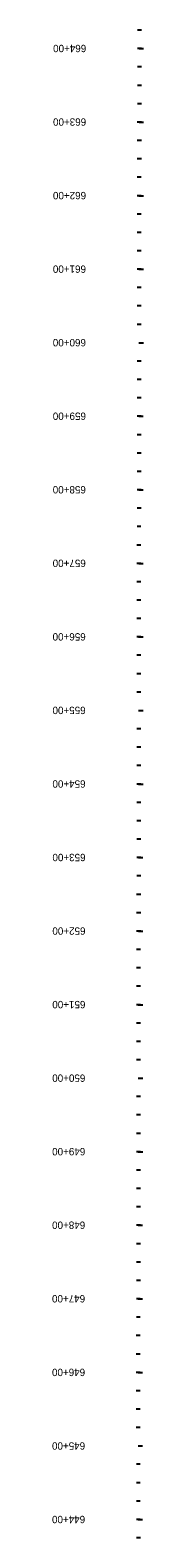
# Model space of a CAD drawing. Extents: x 16453950 to 16454580, y 7022804 to 7039381.
# Drawn here: x 16454322 to 16454446, y 7031115 to 7033165 of the extents above; entities that cross this region are included whole.
import ezdxf

# ---------------------------------------------------------------- set-up
doc = ezdxf.new("R2010")
doc.units = 0
doc.layers.add('TextAlignmentLrg', color=7, linetype='Continuous')
doc.layers.add('TextAlignmentSml', color=7, linetype='Continuous')

msp = doc.modelspace()

# ---------------------------------------------------------------- linework, layer by layer
at = {"layer": 'TextAlignmentLrg'}
for p, q in [((16454442.8, 7033139.6), (16454437.3, 7033139.6)), ((16454442.7, 7033039.6), (16454437.2, 7033039.6)), ((16454442.6, 7032939.6), (16454437.1, 7032939.6)), ((16454442.5, 7032839.6), (16454437.1, 7032839.6)), ((16454439.4, 7032739.6), (16454445.5, 7032739.6)), ((16454442.4, 7032639.6), (16454436.9, 7032639.6)), ((16454442.3, 7032539.6), (16454436.8, 7032539.6)), ((16454442.2, 7032439.6), (16454436.7, 7032439.6)), ((16454442.1, 7032339.6), (16454436.6, 7032339.6)), ((16454439, 7032239.6), (16454445.1, 7032239.6)), ((16454441.9, 7032139.6), (16454436.5, 7032139.6)), ((16454441.9, 7032039.6), (16454436.4, 7032039.6)), ((16454441.8, 7031939.6), (16454436.3, 7031939.6)), ((16454441.7, 7031839.6), (16454436.2, 7031839.6)), ((16454438.5, 7031739.6), (16454444.7, 7031739.6)), ((16454441.5, 7031639.6), (16454436.1, 7031639.6)), ((16454441.4, 7031539.6), (16454436, 7031539.6)), ((16454441.3, 7031439.6), (16454435.9, 7031439.6)), ((16454441.3, 7031339.6), (16454435.8, 7031339.6)), ((16454438.2, 7031239.6), (16454444.4, 7031239.6)), ((16454441.3, 7031139.6), (16454435.9, 7031139.6))]:
    msp.add_line(p, q, dxfattribs=at)
at = {"layer": 'TextAlignmentSml'}
for p, q in [((16454442.8, 7033164.6), (16454437.3, 7033164.6)), ((16454439.7, 7033139.6), (16454445.8, 7033139.6)), ((16454442.8, 7033114.6), (16454437.3, 7033114.6)), ((16454442.7, 7033089.6), (16454437.3, 7033089.6)), ((16454442.7, 7033064.6), (16454437.3, 7033064.6)), ((16454439.6, 7033039.6), (16454445.8, 7033039.6)), ((16454442.7, 7033014.6), (16454437.2, 7033014.6)), ((16454442.7, 7032989.6), (16454437.2, 7032989.6)), ((16454442.6, 7032964.6), (16454437.2, 7032964.6)), ((16454439.5, 7032939.6), (16454445.7, 7032939.6)), ((16454442.6, 7032914.6), (16454437.1, 7032914.6)), ((16454442.6, 7032889.6), (16454437.1, 7032889.6)), ((16454442.5, 7032864.6), (16454437.1, 7032864.6)), ((16454439.5, 7032839.6), (16454445.6, 7032839.6)), ((16454442.5, 7032814.6), (16454437, 7032814.6)), ((16454442.5, 7032789.6), (16454437, 7032789.6)), ((16454442.5, 7032764.6), (16454437, 7032764.6)), ((16454439.4, 7032739.6), (16454445.5, 7032739.6)), ((16454442.4, 7032714.6), (16454437, 7032714.6)), ((16454442.4, 7032689.6), (16454436.9, 7032689.6)), ((16454442.4, 7032664.6), (16454436.9, 7032664.6)), ((16454439.3, 7032639.6), (16454445.4, 7032639.6)), ((16454442.3, 7032614.6), (16454436.9, 7032614.6)), ((16454442.3, 7032589.6), (16454436.9, 7032589.6)), ((16454442.3, 7032564.6), (16454436.8, 7032564.6)), ((16454439.2, 7032539.6), (16454445.3, 7032539.6)), ((16454442.3, 7032514.6), (16454436.8, 7032514.6)), ((16454442.2, 7032489.6), (16454436.8, 7032489.6)), ((16454442.2, 7032464.6), (16454436.7, 7032464.6)), ((16454439.1, 7032439.6), (16454445.2, 7032439.6)), ((16454442.2, 7032414.6), (16454436.7, 7032414.6)), ((16454442.1, 7032389.6), (16454436.7, 7032389.6)), ((16454442.1, 7032364.6), (16454436.7, 7032364.6)), ((16454439, 7032339.6), (16454445.2, 7032339.6)), ((16454442.1, 7032314.6), (16454436.6, 7032314.6)), ((16454442.1, 7032289.6), (16454436.6, 7032289.6)), ((16454442, 7032264.6), (16454436.6, 7032264.6)), ((16454439, 7032239.6), (16454445.1, 7032239.6)), ((16454442, 7032214.6), (16454436.5, 7032214.6)), ((16454442, 7032189.6), (16454436.5, 7032189.6)), ((16454442, 7032164.6), (16454436.5, 7032164.6)), ((16454438.9, 7032139.6), (16454445, 7032139.6)), ((16454441.9, 7032114.6), (16454436.5, 7032114.6)), ((16454441.9, 7032089.6), (16454436.4, 7032089.6)), ((16454441.9, 7032064.6), (16454436.4, 7032064.6)), ((16454438.8, 7032039.6), (16454444.9, 7032039.6)), ((16454441.8, 7032014.6), (16454436.4, 7032014.6)), ((16454441.8, 7031989.6), (16454436.3, 7031989.6)), ((16454441.8, 7031964.6), (16454436.3, 7031964.6)), ((16454438.7, 7031939.6), (16454444.8, 7031939.6)), ((16454441.7, 7031914.6), (16454436.3, 7031914.6)), ((16454441.7, 7031889.6), (16454436.3, 7031889.6)), ((16454441.7, 7031864.6), (16454436.2, 7031864.6)), ((16454438.6, 7031839.6), (16454444.7, 7031839.6)), ((16454441.7, 7031814.6), (16454436.2, 7031814.6)), ((16454441.6, 7031789.6), (16454436.2, 7031789.6)), ((16454441.6, 7031764.6), (16454436.2, 7031764.6)), ((16454438.5, 7031739.6), (16454444.7, 7031739.6)), ((16454441.6, 7031714.6), (16454436.1, 7031714.6)), ((16454441.6, 7031689.6), (16454436.1, 7031689.6)), ((16454441.5, 7031664.6), (16454436.1, 7031664.6)), ((16454438.5, 7031639.6), (16454444.6, 7031639.6)), ((16454441.5, 7031614.6), (16454436, 7031614.6)), ((16454441.5, 7031589.6), (16454436, 7031589.6)), ((16454441.4, 7031564.6), (16454436, 7031564.6)), ((16454438.4, 7031539.6), (16454444.5, 7031539.6)), ((16454441.4, 7031514.6), (16454435.9, 7031514.6)), ((16454441.4, 7031489.6), (16454435.9, 7031489.6)), ((16454441.4, 7031464.6), (16454435.9, 7031464.6)), ((16454438.3, 7031439.6), (16454444.4, 7031439.6)), ((16454441.3, 7031414.6), (16454435.9, 7031414.6)), ((16454441.3, 7031389.6), (16454435.8, 7031389.6)), ((16454441.3, 7031364.6), (16454435.8, 7031364.6)), ((16454438.2, 7031339.6), (16454444.3, 7031339.6)), ((16454441.3, 7031314.6), (16454435.8, 7031314.6)), ((16454441.3, 7031289.6), (16454435.8, 7031289.6)), ((16454441.3, 7031264.6), (16454435.8, 7031264.6)), ((16454438.2, 7031239.6), (16454444.4, 7031239.6)), ((16454441.3, 7031214.6), (16454435.9, 7031214.6)), ((16454441.3, 7031189.6), (16454435.9, 7031189.6)), ((16454441.3, 7031164.6), (16454435.9, 7031164.6)), ((16454438.3, 7031139.6), (16454444.4, 7031139.6)), ((16454441.4, 7031114.6), (16454435.9, 7031114.6))]:
    msp.add_line(p, q, dxfattribs=at)

# ---------------------------------------------------------------- texts
at = {"layer": 'TextAlignmentLrg'}
for s, rotation, p in [('660+00', 179.9517, (16454367.4, 7032744.7)), ('655+00', 179.9517, (16454367, 7032244.7)), ('650+00', 179.9517, (16454366.6, 7031744.7)), ('645+00', 180.0231, (16454366.3, 7031244.6))]:
    msp.add_text(s, height=10.02, rotation=rotation, dxfattribs=at).set_placement(p)
at = {"layer": 'TextAlignmentSml'}
for s, rotation, p in [('664+00', 179.9517, (16454367.8, 7033144.7)), ('663+00', 179.9517, (16454367.7, 7033044.7)), ('662+00', 179.9517, (16454367.6, 7032944.7)), ('661+00', 179.9517, (16454367.5, 7032844.7)), ('660+00', 179.9517, (16454367.4, 7032744.7)), ('659+00', 179.9517, (16454367.4, 7032644.7)), ('658+00', 179.9517, (16454367.3, 7032544.7)), ('657+00', 179.9517, (16454367.2, 7032444.7)), ('656+00', 179.9517, (16454367.1, 7032344.7)), ('655+00', 179.9517, (16454367, 7032244.7)), ('654+00', 179.9517, (16454366.9, 7032144.7)), ('653+00', 179.9517, (16454366.9, 7032044.7)), ('652+00', 179.9517, (16454366.8, 7031944.7)), ('651+00', 179.9517, (16454366.7, 7031844.7)), ('650+00', 179.9517, (16454366.6, 7031744.7)), ('649+00', 179.9517, (16454366.5, 7031644.7)), ('648+00', 179.9517, (16454366.4, 7031544.7)), ('647+00', 179.9517, (16454366.3, 7031444.7)), ('646+00', 180.0231, (16454366.3, 7031344.6)), ('645+00', 180.0231, (16454366.3, 7031244.6)), ('644+00', 180.0231, (16454366.3, 7031144.6))]:
    msp.add_text(s, height=10.02, rotation=rotation, dxfattribs=at).set_placement(p)

doc.saveas('drawing.dxf')
